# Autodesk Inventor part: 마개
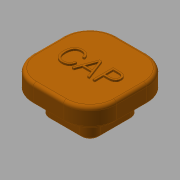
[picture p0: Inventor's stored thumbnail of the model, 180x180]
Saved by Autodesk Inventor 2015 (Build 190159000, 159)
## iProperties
Created: 2018-03
Part Number: 마개
Material: 고무
Document SubType Name: Modeling
Designer: mduedu
Density: 1 g/cm^3
Appearance: 주황색
Author: mduedu
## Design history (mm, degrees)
sketch "스케치1"
  geometry: L1 (12.5, 12.5)-(-12.5, 12.5); L2 (-12.5, 12.5)-(-12.5, -12.5); L3 (-12.5, -12.5)-(12.5, -12.5); L4 (12.5, -12.5)-(12.5, 12.5); L5 (12.5, 12.5)-(-12.5, -12.5); L6 (-12.5, 12.5)-(12.5, -12.5); 1 further point
  constraints: 12 end point, 2 midpoint, 2 parallel, 1 horizontal, 1 perpendicular
  dimensions: "d0" = 25 distance of L3.end L2.end; "d1" = 25 distance of L2.end L1.end
extrude "돌출1" new body sketch "스케치1" distance "d2" = 6; taper "d3" = 0 deg
fillet "모깎기1" dims "d4" = 8
fillet "모깎기2" dims "d5" = 1
sketch "스케치2"
  geometry: L1 (4.5, -12.5)-(-4.5, -12.5) reference; L2 (12.5, 4.5)-(12.5, -4.5) reference; L3 (-4.5, 12.5)-(4.5, 12.5) reference; L4 (-12.5, -4.5)-(-12.5, 4.5) reference; L5 (0, -12.5)-(0, 12.5); L6 (-12.5, 0)-(12.5, 0); C1 r 7.5 at (0, 0); A1 r 8 centre (-4.5, -4.5) between (-12.5, -4.5) and (-4.5, -12.5) reference; A2 r 8 centre (4.5, -4.5) between (4.5, -12.5) and (12.5, -4.5) reference; A3 r 8 centre (4.5, 4.5) between (12.5, 4.5) and (4.5, 12.5) reference; A4 r 8 centre (-4.5, 4.5) between (-4.5, 12.5) and (-12.5, 4.5) reference
  constraints: 5 midpoint, 4 end point, 1 centre point
  dimensions: "d21" = 15 diameter of C1
extrude "돌출2" join sketch "스케치2" distance "d7" = 6; taper "d8" = 0 deg
sketch "스케치3"
  geometry: L1 (4.5, 7.5)-(-4.5, 7.5) reference; L2 (-7.5, 4.5)-(-7.5, -4.5) reference; L3 (-4.5, -7.5)-(4.5, -7.5) reference; L4 (7.5, -4.5)-(7.5, 4.5) reference; C1 r 5.5 at (0, 0); A1 r 3 centre (4.5, 4.5) between (7.5, 4.5) and (4.5, 7.5) reference; A2 r 3 centre (-4.5, 4.5) between (-4.5, 7.5) and (-7.5, 4.5) reference; A3 r 3 centre (-4.5, -4.5) between (-7.5, -4.5) and (-4.5, -7.5) reference; A4 r 3 centre (4.5, -4.5) between (4.5, -7.5) and (7.5, -4.5) reference; 2 further points
  constraints: 1 centre point, 1 vertical alignment
  dimensions: "d22" = 2 dimension on C1
extrude "돌출3" cut sketch "스케치3" stored distance "d10" = 10; taper "d11" = 0 deg
fillet "모깎기3" dims "d12" = 1
sketch "스케치4"
  geometry: L1 (4.5, -12.5)-(-4.5, -12.5) reference; L2 (12.5, 4.5)-(12.5, -4.5) reference; L3 (-4.5, 12.5)-(4.5, 12.5) reference; L4 (-12.5, -4.5)-(-12.5, 4.5) reference; L5 (11.5, 4.5)-(11.5, -4.5); L6 (4.5, -11.5)-(-4.5, -11.5); L7 (-11.5, -4.5)-(-11.5, 4.5); L8 (-4.5, 11.5)-(4.5, 11.5); A1 r 8 centre (-4.5, -4.5) between (-12.5, -4.5) and (-4.5, -12.5) reference; A2 r 8 centre (4.5, -4.5) between (4.5, -12.5) and (12.5, -4.5) reference; A3 r 8 centre (4.5, 4.5) between (12.5, 4.5) and (4.5, 12.5) reference; A4 r 8 centre (-4.5, 4.5) between (-4.5, 12.5) and (-12.5, 4.5) reference; A5 r 7 centre (4.5, 4.5) between (11.5, 4.5) and (4.5, 11.5); A6 r 7 centre (4.5, -4.5) between (4.5, -11.5) and (11.5, -4.5); A7 r 7 centre (-4.5, -4.5) between (-11.5, -4.5) and (-4.5, -11.5); A8 r 7 centre (-4.5, 4.5) between (-4.5, 11.5) and (-11.5, 4.5); 1 further point
  constraints: 8 end point, 8 point on circle, 4 centre point, 7 other
  dimensions: "d13" = 1 distance between parallel lines of L8 L3
extrude "돌출4" cut sketch "스케치4" distance "d14" = 1; taper "d15" = 0 deg
chamfer "모따기1" distance "d16" = 0.5; stored, may be unused: second distance "d17" = 2, angle "d18" = 45 deg
sketch "스케치5"
  geometry: 2 further points
  constraints: 1 coincident, 1 other
feature "엠보싱1" sketch "스케치5" dims "d0" = 25, "d1" = 25, "d19" = 0.5, "d20" = 0
fillet "모깎기4" dims "d23" = 0.5
node "솔리드1"
node "투영된 루프1"
node "투영된 루프2"
node "투영된 루프3"
node "참조1"
